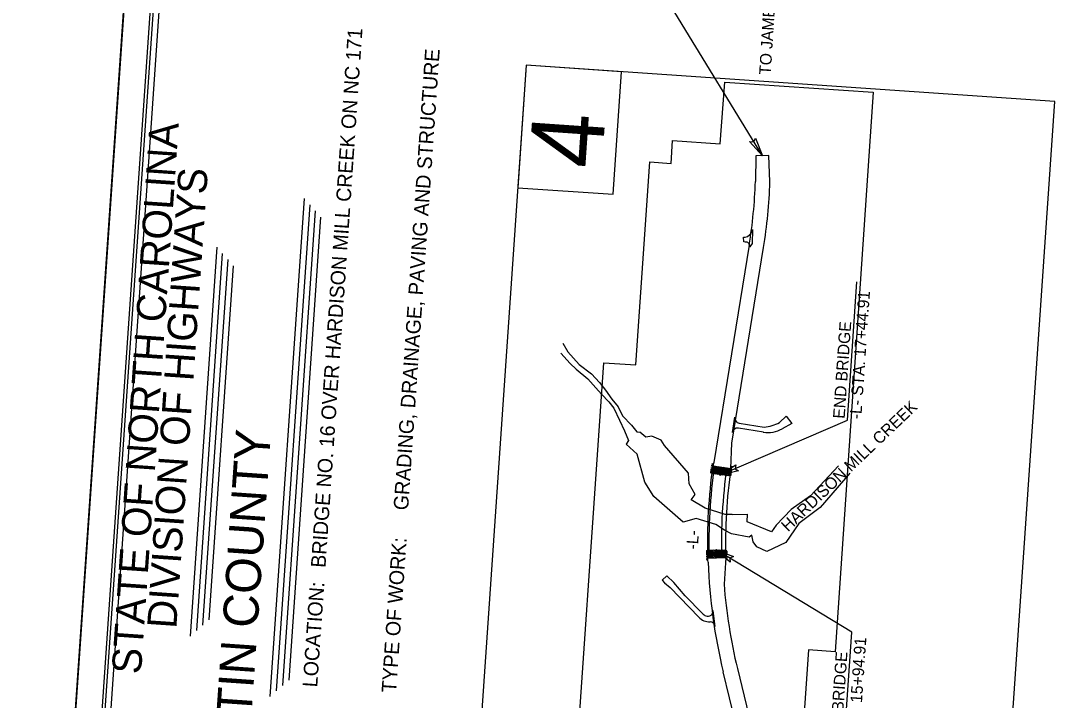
# Model space of a CAD drawing. Extents: x 2598107 to 2605763, y 726018 to 731166.
# Drawn here: x 2598107 to 2600111, y 728931 to 730235 of the extents above; entities that cross this region are included whole.
import ezdxf

# ---------------------------------------------------------------- set-up
doc = ezdxf.new("R2010")
doc.units = 0
for name, color, linetype in [('Old_Level_23', 7, 'Continuous'), ('Old_Level_30', 7, 'Continuous'), ('Old_Level_38', 7, 'Continuous'), ('Old_Level_40', 7, 'Continuous'), ('Old_Level_55', 7, 'Continuous'), ('Old_Level_62', 7, 'Continuous'), ('Prop DGN Element Guardrail', 7, 'Continuous'), ('Prop EOT', 7, 'Continuous'), ('Prop Horizontal Alignment Station Label', 7, 'Continuous'), ('Prop Lane Lines', 7, 'Continuous'), ('Prop Roadway Bridge', 7, 'Continuous'), ('Prop Structure Anchor Unit CELL', 7, 'Continuous'), ('Prop Terminator CELL', 7, 'Continuous'), ('Sheet Cutting Line CELL', 7, 'Continuous'), ('Sheet Plot Border Inside CELL', 7, 'Continuous'), ('Sheet Plot Border Outside CELL', 7, 'Continuous'), ('Sheet Title CELL', 7, 'Continuous'), ('Sheet Title Data Points CELL', 7, 'Continuous')]:
    doc.layers.add(name, color=color, linetype=linetype)

msp = doc.modelspace()

# ---------------------------------------------------------------- linework, layer by layer
at = {"layer": 'Old_Level_23'}
for points in [[(2599990.3, 728580.2), (2600093.6, 730080.2), (2599077.8, 730150.2), (2598974.5, 728650.2)], [(2599244.7, 729902.2), (2599260.9, 730137.6), (2599077.8, 730150.2), (2599061.6, 729914.9)]]:
    msp.add_lwpolyline(points, close=True, dxfattribs=at)
at = {"layer": 'Old_Level_40'}
for p, q in [((2599531.5, 729976.3), (2599363.2, 730251.5)), ((2599694.7, 729468.6), (2599713, 729733.9)), ((2599449.7, 729362.9), (2599694.7, 729468.6)), ((2599703.5, 729061.1), (2599442.9, 729219.1)), ((2599685.1, 728794.3), (2599703.5, 729061.1))]:
    msp.add_line(p, q, dxfattribs=at)
at = {"layer": 'Old_Level_55'}
for p, q in [((2599677.4, 729380.6), (2599623.9, 729322.9)), ((2599623.9, 729322.9), (2599586.7, 729296.6)), ((2599473.4, 729287.1), (2599502.8, 729287.7)), ((2599473.4, 729287.1), (2599502.8, 729287.7)), ((2599502.1, 729273.1), (2599502.8, 729287.7)), ((2599502.1, 729273.1), (2599502.8, 729287.7))]:
    msp.add_line(p, q, dxfattribs=at)
for points in [[(2599147.8, 729616.1), (2599157.5, 729599.6), (2599179.1, 729575.1), (2599202.8, 729557.1), (2599218.6, 729540.5), (2599229.9, 729526.2), (2599242, 729508.6), (2599254.1, 729494.1), (2599262.9, 729476.4), (2599280, 729458.5), (2599289.9, 729446.2), (2599296.1, 729445.3)], [(2599143.9, 729596.9), (2599161.9, 729577), (2599173.7, 729566.6), (2599195.8, 729547.5), (2599211.4, 729530.6), (2599222.6, 729518.3), (2599236.2, 729503.9), (2599245.9, 729491.5), (2599257.1, 729468.7), (2599266.6, 729447.6), (2599273.9, 729429.5), (2599269.9, 729422)], [(2599473.4, 729287.1), (2599460.2, 729287.2), (2599421.4, 729299.3), (2599394.8, 729315.5), (2599402.6, 729325.4), (2599390.5, 729345.9), (2599389.6, 729366.6), (2599343.6, 729419.9), (2599336.9, 729430.3), (2599318.9, 729437.8), (2599307.6, 729435.5), (2599296.1, 729445.3)], [(2599471.8, 729250), (2599458.7, 729257), (2599442, 729268.1), (2599404.3, 729279.3), (2599379, 729272.2), (2599322.6, 729322.1), (2599305.7, 729349.5), (2599290.8, 729403.3), (2599269.9, 729422)], [(2599699.6, 729366.7), (2599642.2, 729300.5), (2599601.4, 729270.1), (2599576.5, 729233.7), (2599540.1, 729216.4), (2599520.5, 729225), (2599513.5, 729234.7), (2599511, 729247.3), (2599506, 729244), (2599471.8, 729250)], [(2599586.7, 729296.6), (2599557.9, 729267), (2599548.9, 729253.7), (2599502.1, 729273.1)]]:
    msp.add_lwpolyline(points, dxfattribs=at)
at = {"layer": 'Old_Level_62'}
msp.add_lwpolyline([(2599163.1, 728657.9), (2599226.5, 729578.6), (2599288.2, 729574.4), (2599315.1, 729964.7), (2599355.9, 729961.4), (2599358.9, 730005.2), (2599450.2, 729998.9), (2599459.4, 730117.6), (2599744.2, 730098), (2599671.1, 729023.8), (2599619.8, 729027.4), (2599592.3, 728628.3)], close=True, dxfattribs=at)
at = {"layer": 'Prop DGN Element Guardrail'}
for p, q in [((2599434.2, 729365.7), (2599436.7, 729384.2)), ((2599468.9, 729361.2), (2599471.4, 729379.8))]:
    msp.add_line(p, q, dxfattribs=at)
at = {"layer": 'Prop EOT'}
for p, q in [((2599519.1, 729976), (2599517.9, 729926.7)), ((2599543.9, 729976.6), (2599519.1, 729976)), ((2599545.9, 729925.9), (2599543.9, 729976.6)), ((2599512.5, 729834.5), (2599512.1, 729807.9)), ((2599495.1, 729819.6), (2599498.6, 729819.9)), ((2599495.5, 729810.7), (2599495.1, 729819.6)), ((2599498.6, 729819.9), (2599503, 729821.4)), ((2599503, 729821.4), (2599507.2, 729824.8)), ((2599506.1, 729804.4), (2599438.1, 729387.3)), ((2599472.5, 729424.5), (2599533.7, 729799.9)), ((2599498.2, 729810.5), (2599495.5, 729810.7)), ((2599500.4, 729810.3), (2599498.2, 729810.5)), ((2599512.1, 729807.9), (2599507.6, 729801)), ((2599473.8, 729444.7), (2599478.6, 729474.3)), ((2599564.3, 729464.1), (2599577.3, 729475.9)), ((2599577.3, 729475.9), (2599587.8, 729462.2)), ((2599533.3, 729445.2), (2599485.3, 729453)), ((2599486.9, 729462.9), (2599534.9, 729455)), ((2599587.8, 729462.2), (2599569.4, 729451.7)), ((2599470.9, 729375.8), (2599472.5, 729424.5)), ((2599438.1, 729387.3), (2599436.2, 729380.7)), ((2599436.2, 729380.7), (2599470.9, 729375.8)), ((2599426.2, 729203.1), (2599461.1, 729204.4)), ((2599427.4, 729195.6), (2599426.2, 729203.1)), ((2599461.1, 729204.4), (2599457.8, 729153.6)), ((2599347.7, 729169.4), (2599338.9, 729160.9)), ((2599338.9, 729160.9), (2599343.5, 729156.3)), ((2599343.5, 729156.3), (2599354.2, 729146.9)), ((2599361.3, 729156.4), (2599347.7, 729169.4)), ((2599383.3, 729131.2), (2599361.3, 729156.4)), ((2599354.2, 729146.9), (2599409.2, 729090.1)), ((2599416.4, 729097), (2599383.3, 729131.2)), ((2599441, 729072.4), (2599436.7, 729103)), ((2599492.1, 728836.3), (2599456.2, 728985)), ((2599483.4, 728991.6), (2599519.3, 728842.9))]:
    msp.add_line(p, q, dxfattribs=at)
for centre, radius, start, end in [((2598577.4, 729955.9), 941, 350.7363, 358.2243), ((2598577.4, 729955.9), 969, 350.7363, 358.2243), ((2599497.7, 729836.4), 15, 309.3389, 352.6025), ((2599499.7, 729802.3), 8, 350.7363, 84.8302), ((2599488.5, 729472.7), 10, 170.7363, 260.7363), ((2599483.7, 729443.1), 10, 80.7363, 170.7363), ((2599530.3, 729522.4), 67.5, 273.897, 300.2904), ((2599542.1, 729499.5), 55, 260.7363, 299.81), ((2600480.7, 729232.5), 1054, 182.0052, 193.5781), ((2600480.7, 729232.5), 1026, 184.408, 193.5781), ((2599430.7, 729110.9), 20, 224.0417, 246.9931), ((2599426.8, 729101.7), 10, 246.9931, 7.072), ((2599430.7, 729110.9), 30, 224.0417, 270.5306), ((2599431.1, 729070.9), 10, 8.7494, 90.5306)]:
    msp.add_arc(centre, radius, start, end, dxfattribs=at)
at = {"layer": 'Prop Lane Lines'}
for radius, end in [(1052, 181.5949), (1028, 181.5825)]:
    msp.add_arc((2600480.7, 729232.5), radius, 171.9208, end, dxfattribs=at)
at = {"layer": 'Prop Roadway Bridge'}
for p, q in [((2599443.5, 729364.5), (2599435.3, 729373.9)), ((2599446.5, 729364.1), (2599435.6, 729376.5)), ((2599449.5, 729363.7), (2599436, 729379.2)), ((2599452.4, 729363.3), (2599437.4, 729380.6)), ((2599455.4, 729363), (2599440.5, 729380.1)), ((2599458.4, 729362.6), (2599443.5, 729379.7)), ((2599461.4, 729362.2), (2599446.5, 729379.3)), ((2599464.4, 729361.8), (2599449.5, 729378.9)), ((2599467.4, 729361.4), (2599452.6, 729378.4)), ((2599469.1, 729362.5), (2599455.6, 729378)), ((2599469.4, 729365.2), (2599458.6, 729377.6)), ((2599469.8, 729367.8), (2599461.7, 729377.1)), ((2599470.1, 729370.4), (2599464.7, 729376.7)), ((2599470.5, 729373.1), (2599467.7, 729376.3)), ((2599470.8, 729375.3), (2599470.3, 729375.9)), ((2599468.9, 729361.2), (2599434.2, 729365.7)), ((2599437.5, 729365.2), (2599434.6, 729368.6)), ((2599440.5, 729364.9), (2599434.9, 729371.3)), ((2599425.8, 729218.9), (2599460.8, 729219.4)), ((2599441.7, 729203.7), (2599425.8, 729218.9)), ((2599438.9, 729203.6), (2599425.9, 729216.1)), ((2599436.1, 729203.5), (2599425.9, 729213.2)), ((2599444.5, 729203.8), (2599428.6, 729219)), ((2599447.2, 729203.9), (2599431.5, 729219)), ((2599450, 729204), (2599434.3, 729219)), ((2599452.8, 729204.1), (2599437.2, 729219.1)), ((2599455.6, 729204.2), (2599440, 729219.1)), ((2599458.4, 729204.3), (2599442.9, 729219.1)), ((2599461.1, 729204.4), (2599445.7, 729219.2)), ((2599461.1, 729207.2), (2599448.6, 729219.2)), ((2599461, 729210.1), (2599451.4, 729219.3)), ((2599460.9, 729212.9), (2599454.3, 729219.3)), ((2599460.9, 729215.7), (2599457.1, 729219.3)), ((2599460.8, 729218.5), (2599460, 729219.4)), ((2599433.3, 729203.3), (2599426, 729210.4)), ((2599430.6, 729203.2), (2599426, 729207.6)), ((2599427.8, 729203.1), (2599426.1, 729204.7))]:
    msp.add_line(p, q, dxfattribs=at)
for radius, end in [(1055, 181.5964), (1020, 181.5783)]:
    msp.add_arc((2600480.7, 729232.5), radius, 171.9208, end, dxfattribs=at)
at = {"layer": 'Prop Structure Anchor Unit CELL'}
for p, q in [((2599433, 729371.6), (2599433.1, 729372.7)), ((2599433.2, 729373.1), (2599433.3, 729374.2)), ((2599435.2, 729373.4), (2599433.2, 729373.7)), ((2599433.4, 729374.7), (2599433.5, 729375.8)), ((2599435.4, 729375), (2599433.5, 729375.2)), ((2599433.8, 729377.8), (2599433.9, 729378.9)), ((2599435.9, 729378.1), (2599433.9, 729378.3)), ((2599434.2, 729365.7), (2599436.7, 729384.2)), ((2599434.2, 729380.8), (2599434.4, 729382)), ((2599436.3, 729381.1), (2599434.3, 729381.4)), ((2599434.6, 729383.9), (2599434.8, 729385.1)), ((2599436.7, 729384.2), (2599434.7, 729384.5)), ((2599468.9, 729361.2), (2599471.4, 729379.8)), ((2599470.6, 729373.6), (2599472.6, 729373.4)), ((2599471, 729376.7), (2599473, 729376.5)), ((2599471.4, 729379.8), (2599473.4, 729379.6)), ((2599472.5, 729372.8), (2599472.6, 729373.9)), ((2599472.9, 729375.9), (2599473, 729377)), ((2599473.3, 729379), (2599473.5, 729380.1)), ((2599432.3, 729366.9), (2599432.5, 729368)), ((2599434.4, 729367.2), (2599432.4, 729367.5)), ((2599432.5, 729368.5), (2599432.7, 729369.6)), ((2599434.6, 729368.8), (2599432.6, 729369)), ((2599432.8, 729370), (2599432.9, 729371.1)), ((2599434.8, 729370.3), (2599432.8, 729370.6)), ((2599435, 729371.9), (2599433, 729372.1)), ((2599469.1, 729362.8), (2599471.1, 729362.5)), ((2599469.3, 729364.3), (2599471.3, 729364.1)), ((2599469.5, 729365.9), (2599471.5, 729365.6)), ((2599469.7, 729367.4), (2599471.7, 729367.2)), ((2599469.9, 729369), (2599471.9, 729368.7)), ((2599470.2, 729370.5), (2599472.1, 729370.3)), ((2599471, 729362), (2599471.2, 729363.1)), ((2599471.2, 729363.5), (2599471.4, 729364.6)), ((2599471.4, 729365.1), (2599471.6, 729366.2)), ((2599471.6, 729366.6), (2599471.8, 729367.7)), ((2599471.9, 729368.2), (2599472, 729369.3)), ((2599472.1, 729369.7), (2599472.2, 729370.8)), ((2599423.9, 729217.9), (2599423.9, 729216.8)), ((2599425.9, 729217.4), (2599423.9, 729217.3)), ((2599423.9, 729216.3), (2599423.9, 729215.2)), ((2599425.9, 729215.8), (2599423.9, 729215.8)), ((2599423.9, 729214.8), (2599423.9, 729213.6)), ((2599425.9, 729214.2), (2599423.9, 729214.2)), ((2599423.9, 729213.2), (2599424, 729212.1)), ((2599426, 729212.7), (2599424, 729212.6)), ((2599425.8, 729218.9), (2599426.2, 729200.2)), ((2599460.8, 729219.4), (2599461.2, 729200.6)), ((2599460.9, 729217.8), (2599462.9, 729217.9)), ((2599460.9, 729216.3), (2599462.9, 729216.3)), ((2599460.9, 729214.7), (2599462.9, 729214.7)), ((2599461, 729213.1), (2599463, 729213.2)), ((2599462.8, 729218.4), (2599462.9, 729217.3)), ((2599462.9, 729216.9), (2599462.9, 729215.7)), ((2599462.9, 729215.3), (2599462.9, 729214.2)), ((2599462.9, 729213.7), (2599463, 729212.6)), ((2599463, 729212.2), (2599463, 729211)), ((2599424, 729211.7), (2599424, 729210.5)), ((2599426, 729211.1), (2599424, 729211.1)), ((2599424, 729210.1), (2599424, 729208.9)), ((2599426, 729209.6), (2599424, 729209.5)), ((2599424.1, 729207), (2599424.1, 729205.8)), ((2599426.1, 729206.4), (2599424.1, 729206.4)), ((2599424.1, 729203.8), (2599424.2, 729202.7)), ((2599426.1, 729203.3), (2599424.1, 729203.3)), ((2599424.2, 729200.7), (2599424.2, 729199.6)), ((2599426.2, 729200.2), (2599424.2, 729200.1)), ((2599461, 729211.6), (2599463, 729211.6)), ((2599461, 729210), (2599463, 729210)), ((2599461.1, 729206.9), (2599463.1, 729206.9)), ((2599461.1, 729203.8), (2599463.1, 729203.8)), ((2599461.2, 729200.6), (2599463.2, 729200.7)), ((2599463, 729210.6), (2599463, 729209.5)), ((2599463.1, 729207.5), (2599463.1, 729206.3)), ((2599463.1, 729204.4), (2599463.2, 729203.2)), ((2599463.2, 729201.2), (2599463.2, 729200.1))]:
    msp.add_line(p, q, dxfattribs=at)
at = {"layer": 'Prop Terminator CELL'}
for points in [[(2599517.9, 730010.2), (2599531.5, 729976.3), (2599507, 730003.7), (2599514.9, 730003.2)], [(2599485.3, 729370.9), (2599449.7, 729362.9), (2599480.7, 729382.6), (2599478.9, 729375)], [(2599469.5, 729195.8), (2599441.7, 729219.4), (2599476.1, 729206.5), (2599468.9, 729203.3)]]:
    msp.add_lwpolyline(points, close=True, dxfattribs=at)
at = {"layer": 'Sheet Cutting Line CELL'}
msp.add_line((2598106.6, 727386), (2598366.9, 731166.1), dxfattribs=at)
at = {"layer": 'Sheet Plot Border Inside CELL'}
msp.add_lwpolyline([(2600527.3, 727248.6), (2600785, 730989.4), (2598416.6, 731152.5), (2598159, 727411.7)], close=True, dxfattribs=at)
at = {"layer": 'Sheet Plot Border Outside CELL'}
msp.add_lwpolyline([(2598366.9, 731166.1), (2598106.6, 727386), (2600575.7, 727216), (2600836, 730996)], close=True, dxfattribs=at)
at = {"layer": 'Sheet Title CELL'}
for p, q in [((2598585.9, 728938), (2598651.8, 729894.2)), ((2598597.9, 728948.4), (2598662.2, 729882.2)), ((2598609.9, 728958.9), (2598672.7, 729870.2)), ((2598621.9, 728969.3), (2598683.1, 729858.2)), ((2598432.4, 729053.7), (2598483.8, 729800.7)), ((2598444.4, 729064.2), (2598494.3, 729788.7)), ((2598456.4, 729074.6), (2598504.7, 729776.7)), ((2598468.4, 729085.1), (2598515.2, 729764.7))]:
    msp.add_line(p, q, dxfattribs=at)
for points in [[(2598418.9, 731101.6), (2598190, 727779.5)], [(2598429.3, 731089.6), (2598209.8, 727902.2)]]:
    msp.add_lwpolyline(points, dxfattribs=at)
at = {"layer": 'Sheet Title Data Points CELL'}
for p, q in [((2598726.2, 729682.9), (2598726.2, 729682.9)), ((2598585.6, 729421.9), (2598585.6, 729421.9))]:
    msp.add_line(p, q, dxfattribs=at)

# ---------------------------------------------------------------- texts
at = {"layer": 'Old_Level_23'}
for s, height, rotation, p in [('TO JAMESVILLE', 22.5, 86.4605, (2599547.5, 730131)), ('4', 140, 86.0601, (2599222.7, 729949.9))]:
    msp.add_text(s, height=height, rotation=rotation, dxfattribs=at).set_placement(p)
at = {"layer": 'Old_Level_30'}
msp.add_text('HARDISON MILL CREEK', height=22.5, rotation=43.5984, dxfattribs=at).set_placement((2599580.6, 729252.8))
at = {"layer": 'Old_Level_38'}
for s, height, p in [('BRIDGE NO. 16 OVER HARDISON MILL CREEK ON NC 171', 28.125, (2598691.8, 729184.3)), ('GRADING, DRAINAGE, PAVING AND STRUCTURE ', 28.125, (2598850.6, 729294.7)), ('-L- STA. 17+44.91', 22.5, (2599721.4, 729469.7)), ('END BRIDGE', 22.5, (2599689.5, 729470.7)), ('        MARTIN COUNTY        ', 67.5, (2598521.9, 728497.4)), ('-L- STA. 15+94.91', 22.5, (2599714.5, 728804.8)), ('BEGIN BRIDGE', 22.5, (2599680.1, 728806.5))]:
    msp.add_text(s, height=height, rotation=86.0601, dxfattribs=at).set_placement(p)
at = {"layer": 'Prop Horizontal Alignment Station Label'}
msp.add_text('-L-', height=22.5, rotation=85.9773, dxfattribs=at).set_placement((2599407.2, 729219.6))
msp.add_text('-L-', height=22.5, rotation=85.9773, dxfattribs=at).set_placement((2599407.2, 729219.6))
at = {"layer": 'Sheet Title CELL'}
for s, height, p in [('STATE OF NORTH CAROLINA', 56.25, (2598337.2, 728979.6)), ('DIVISION OF HIGHWAYS', 56.25, (2598405.2, 729067.1)), ('TYPE OF WORK:', 28.125, (2598827.6, 728944.3)), ('LOCATION: ', 28.13, (2598676, 728954.8))]:
    msp.add_text(s, height=height, rotation=86.0601, dxfattribs=at).set_placement(p)

doc.saveas('drawing.dxf')
